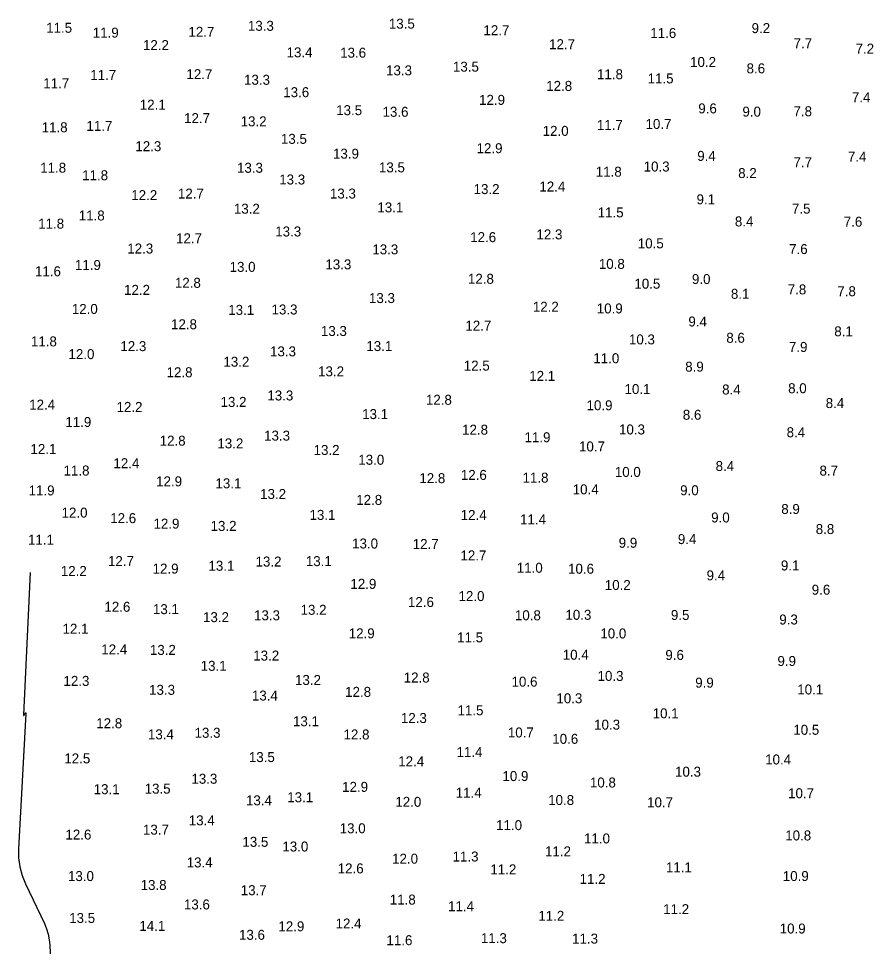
# Model space of a CAD drawing. Extents: x 1023796 to 1112670, y 656573 to 837340.
# Drawn here: x 1112001.4 to 1112430.1, y 656973.6 to 657439 of the extents above; entities that cross this region are included whole.
import ezdxf

# ---------------------------------------------------------------- set-up
doc = ezdxf.new("R2010")
doc.units = 0
doc.layers.add('V-CHAN-CONT-15FT', color=7, linetype='Continuous')
doc.layers.add('V-TOPO-SOUN', color=7, linetype='Continuous')

msp = doc.modelspace()

# ---------------------------------------------------------------- linework, layer by layer
at = {"layer": 'V-CHAN-CONT-15FT'}
msp.add_lwpolyline([(1112007.17, 657161.14), (1112003.86, 657089.72), (1112003.87, 657089.49), (1112003.92, 657089.4), (1112004.02, 657089.44), (1112004.15, 657089.62), (1112004.79, 657090.6), (1112004.93, 657090.78), (1112005.03, 657090.82), (1112005.08, 657090.73), (1112005.08, 657090.51), (1112001.4, 657022.59), (1112001.43, 657018.02), (1112002.02, 657013.57), (1112003.17, 657009.22), (1112004.88, 657004.98), (1112014.39, 656985.07), (1112015.48, 656982.45), (1112016.29, 656979.77), (1112016.83, 656977.01), (1112017.08, 656974.19), (1112017.71, 656958.8)], dxfattribs=at)

# ---------------------------------------------------------------- texts
at = {"layer": 'V-TOPO-SOUN'}
for s, p in [('13.5 ', (1112187.12, 657433.95)), ('11.5 ', (1112015.25, 657431.9)), ('11.9 ', (1112038.62, 657429.48)), ('12.7 ', (1112086.6, 657429.86)), ('13.3 ', (1112116.43, 657432.88)), ('12.7 ', (1112234.56, 657430.68)), ('11.6 ', (1112318.23, 657429.28)), ('9.2', (1112369.05, 657431.73)), ('7.7', (1112390.11, 657424.13)), ('12.2 ', (1112063.8, 657423.21)), ('13.4 ', (1112135.83, 657419.56)), ('13.6 ', (1112162.69, 657419.41)), ('12.7 ', (1112267.48, 657423.66)), ('7.2', (1112421.19, 657421.44)), ('10.2 ', (1112338.2, 657414.73)), ('13.3 ', (1112185.71, 657410.53)), ('13.5 ', (1112219.26, 657412.4)), ('8.6', (1112366.52, 657411.54)), ('11.7 ', (1112037.34, 657408.21)), ('12.7 ', (1112085.6, 657408.63)), ('13.3 ', (1112114.49, 657405.81)), ('11.8 ', (1112291.53, 657408.6)), ('11.5 ', (1112316.89, 657406.49)), ('11.7 ', (1112013.79, 657404.06)), ('12.8 ', (1112266.03, 657402.75)), ('13.6 ', (1112134.15, 657399.59)), ('7.4', (1112419.35, 657397.06)), ('12.1 ', (1112062.21, 657393.32)), ('12.9 ', (1112232.36, 657395.75)), ('9.6', (1112342.31, 657391.46)), ('12.7 ', (1112084.43, 657386.59)), ('13.5 ', (1112160.69, 657390.57)), ('13.6 ', (1112183.95, 657389.76)), ('9.0', (1112364.44, 657389.84)), ('7.8', (1112390.05, 657390.03)), ('11.8 ', (1112012.99, 657381.99)), ('11.7 ', (1112035.46, 657382.7)), ('13.2 ', (1112112.78, 657384.98)), ('11.7 ', (1112291.44, 657383.16)), ('10.7 ', (1112315.85, 657383.65)), ('12.0 ', (1112264.25, 657380.19)), ('13.5 ', (1112132.99, 657376.19)), ('12.3 ', (1112059.98, 657372.51)), ('13.9 ', (1112159.11, 657368.75)), ('12.9 ', (1112231.1, 657371.5)), ('9.4', (1112341.78, 657367.64)), ('7.7', (1112390.06, 657364.47)), ('7.4', (1112417.35, 657367.27)), ('11.8 ', (1112012.24, 657361.71)), ('13.3 ', (1112110.95, 657361.67)), ('13.5 ', (1112182.15, 657361.87)), ('11.8 ', (1112290.89, 657359.71)), ('10.3 ', (1112314.91, 657362.31)), ('8.2', (1112362.32, 657359.02)), ('11.8 ', (1112033.29, 657357.93)), ('13.3 ', (1112132.13, 657355.8)), ('13.2 ', (1112229.62, 657350.98)), ('12.4 ', (1112262.6, 657352.27)), ('12.2 ', (1112057.93, 657347.95)), ('12.7 ', (1112081.32, 657348.73)), ('13.3 ', (1112157.56, 657348.76)), ('9.1', (1112341.44, 657345.87)), ('13.2 ', (1112109.4, 657341.14)), ('13.1 ', (1112181.35, 657341.81)), ('7.5', (1112389.29, 657341.18)), ('11.8 ', (1112031.59, 657337.75)), ('11.5 ', (1112291.86, 657339.29)), ('11.8 ', (1112011.23, 657333.66)), ('8.4', (1112360.66, 657334.77)), ('7.6', (1112415.26, 657334.63)), ('12.7 ', (1112080.39, 657326.31)), ('13.3 ', (1112130.13, 657329.72)), ('12.6 ', (1112227.91, 657326.88)), ('12.3 ', (1112261.15, 657328.26)), ('10.5 ', (1112311.96, 657323.75)), ('12.3 ', (1112055.93, 657321.18)), ('13.3 ', (1112178.83, 657320.75)), ('7.6', (1112387.86, 657320.9)), ('11.9 ', (1112029.67, 657312.92)), ('13.3 ', (1112155.29, 657313.22)), ('10.8 ', (1112292.43, 657313.46)), ('11.6 ', (1112009.64, 657309.77)), ('13.0 ', (1112107.25, 657311.98)), ('12.8 ', (1112079.8, 657303.98)), ('12.8 ', (1112226.78, 657305.99)), ('10.5 ', (1112310.26, 657303.52)), ('9.0', (1112339.12, 657305.87)), ('12.2 ', (1112054.32, 657300.44)), ('8.1', (1112358.67, 657298.46)), ('7.8', (1112387.17, 657300.68)), ('7.8', (1112412.04, 657299.77)), ('13.3 ', (1112177.14, 657296.33)), ('12.0 ', (1112028.11, 657290.87)), ('13.1 ', (1112106.57, 657290.41)), ('13.3 ', (1112128.27, 657290.6)), ('12.2 ', (1112259.32, 657291.97)), ('10.9 ', (1112291.4, 657291.13)), ('9.4', (1112337.34, 657284.57)), ('12.8 ', (1112077.87, 657283.19)), ('13.3 ', (1112153.04, 657279.82)), ('12.7 ', (1112225.49, 657282.5)), ('8.1', (1112410.52, 657279.65)), ('10.3 ', (1112307.53, 657275.59)), ('8.6', (1112356.36, 657276.4)), ('11.8 ', (1112007.59, 657274.6)), ('12.3 ', (1112052.47, 657272.21)), ('13.1 ', (1112175.83, 657272.26)), ('7.9', (1112387.76, 657271.82)), ('12.0 ', (1112026.43, 657268.21)), ('13.3 ', (1112127.52, 657269.59)), ('11.0 ', (1112289.66, 657266.15)), ('13.2 ', (1112104.15, 657264.39)), ('12.5 ', (1112224.69, 657262.44)), ('8.9', (1112335.75, 657261.93)), ('12.8 ', (1112075.63, 657259.12)), ('13.2 ', (1112151.63, 657259.56)), ('12.1 ', (1112257.53, 657257.29)), ('13.3 ', (1112126.18, 657247.47)), ('10.1 ', (1112305.31, 657250.69)), ('8.4', (1112354.27, 657250.46)), ('8.0', (1112387.37, 657251.11)), ('12.4 ', (1112006.74, 657242.89)), ('13.2 ', (1112102.7, 657244.24)), ('12.8 ', (1112205.71, 657245.3)), ('10.9 ', (1112286.26, 657242.56)), ('8.4', (1112406.2, 657243.66)), ('12.2 ', (1112050.54, 657241.72)), ('13.1 ', (1112173.73, 657238.14)), ('8.6', (1112334.55, 657237.8)), ('11.9 ', (1112024.86, 657234.18)), ('12.8 ', (1112223.84, 657230.31)), ('10.3 ', (1112302.55, 657230.42)), ('8.4', (1112386.61, 657229.03)), ('12.8 ', (1112072.18, 657224.8)), ('13.3 ', (1112124.55, 657227.33)), ('11.9 ', (1112255.15, 657226.52)), ('12.1 ', (1112007.37, 657220.63)), ('13.2 ', (1112101.12, 657223.43)), ('13.2 ', (1112149.38, 657220.13)), ('10.7 ', (1112282.48, 657221.91)), ('13.0 ', (1112171.79, 657215.22)), ('11.8 ', (1112023.96, 657209.82)), ('12.4 ', (1112048.98, 657213.49)), ('8.4', (1112351.01, 657212.09)), ('8.7', (1112403.1, 657209.79)), ('12.8 ', (1112202.41, 657205.99)), ('12.6 ', (1112223.23, 657207.62)), ('11.8 ', (1112254.16, 657206.26)), ('10.0 ', (1112300.45, 657209.12)), ('12.9 ', (1112070.39, 657204.4)), ('13.1 ', (1112100.16, 657203.41)), ('11.9 ', (1112006.44, 657199.85)), ('13.2 ', (1112122.55, 657198.06)), ('10.4 ', (1112279.32, 657200.38)), ('9.0', (1112333.22, 657199.94)), ('12.8 ', (1112170.75, 657195.1)), ('12.0 ', (1112022.97, 657188.72)), ('13.1 ', (1112147.31, 657187.57)), ('12.4 ', (1112223.14, 657187.52)), ('8.9', (1112383.93, 657190.54)), ('12.6 ', (1112047.38, 657185.94)), ('12.9 ', (1112069.07, 657183.2)), ('13.2 ', (1112097.7, 657182.05)), ('11.4 ', (1112252.91, 657185.31)), ('9.0', (1112348.77, 657186.28)), ('8.8', (1112401.21, 657180.47)), ('11.1 ', (1112006.12, 657175.13)), ('13.0 ', (1112168.68, 657173.22)), ('12.7 ', (1112199.08, 657172.98)), ('9.9', (1112302.38, 657173.59)), ('9.4', (1112332.06, 657175.43)), ('12.7 ', (1112046.25, 657164.42)), ('13.2 ', (1112120.25, 657164.17)), ('13.1 ', (1112145.48, 657164.38)), ('12.7 ', (1112223.03, 657167.24)), ('12.2 ', (1112022.6, 657159.44)), ('12.9 ', (1112068.63, 657160.63)), ('13.1 ', (1112096.64, 657162.05)), ('11.0 ', (1112251.27, 657161.05)), ('10.6 ', (1112276.99, 657160.56)), ('9.1', (1112383.75, 657162.21)), ('9.4', (1112346.47, 657157.24)), ('12.9 ', (1112167.82, 657152.98)), ('10.2 ', (1112295.42, 657152.4)), ('9.6', (1112399.2, 657150.04)), ('12.0 ', (1112222.06, 657146.85)), ('12.6 ', (1112044.45, 657141.48)), ('13.1 ', (1112068.8, 657140.3)), ('13.2 ', (1112142.84, 657139.96)), ('12.6 ', (1112196.7, 657143.87)), ('13.2 ', (1112093.92, 657136.28)), ('13.3 ', (1112119.5, 657137.21)), ('10.8 ', (1112250.34, 657137.23)), ('10.3 ', (1112275.67, 657137.46)), ('9.5', (1112328.58, 657137.38)), ('9.3', (1112382.94, 657135.1)), ('12.1 ', (1112023.46, 657130.47)), ('12.9 ', (1112167, 657128.17)), ('11.5 ', (1112221.36, 657126.12)), ('10.0 ', (1112293.18, 657128.11)), ('12.4 ', (1112042.89, 657120.1)), ('13.2 ', (1112067.26, 657119.86)), ('13.2 ', (1112119.1, 657117.01)), ('10.4 ', (1112274.33, 657117.42)), ('9.6', (1112325.79, 657117.33)), ('9.9', (1112382.01, 657114.29)), ('13.1 ', (1112092.73, 657111.86)), ('12.3 ', (1112023.92, 657104.31)), ('13.2 ', (1112140.05, 657104.78)), ('12.8 ', (1112194.56, 657106)), ('10.6 ', (1112248.64, 657103.92)), ('10.3 ', (1112291.78, 657106.8)), ('9.9', (1112340.77, 657103.44)), ('13.3 ', (1112066.86, 657099.83)), ('12.8 ', (1112165.19, 657098.8)), ('10.1 ', (1112391.94, 657100.01)), ('13.4 ', (1112118.44, 657096.97)), ('10.3 ', (1112271.13, 657095.59)), ('11.5 ', (1112221.55, 657089.55)), ('13.1 ', (1112139.03, 657084.07)), ('12.3 ', (1112193.15, 657085.69)), ('10.1 ', (1112319.42, 657088.05)), ('12.8 ', (1112040.37, 657083.07)), ('10.3 ', (1112290.07, 657082.36)), ('10.5 ', (1112389.96, 657079.78)), ('13.4 ', (1112066.28, 657077.48)), ('13.3 ', (1112089.66, 657078.28)), ('12.8 ', (1112164.39, 657077.44)), ('10.7 ', (1112246.8, 657078.44)), ('10.6 ', (1112269.08, 657075.24)), ('12.5 ', (1112024.35, 657065.44)), ('13.5 ', (1112116.91, 657066.1)), ('11.4 ', (1112221.06, 657068.62)), ('12.4 ', (1112191.83, 657063.97)), ('10.4 ', (1112375.84, 657064.89)), ('10.9 ', (1112244.09, 657056.57)), ('10.3 ', (1112330.65, 657058.75)), ('13.3 ', (1112088.09, 657055.22)), ('10.8 ', (1112287.95, 657053.35)), ('13.1 ', (1112039.07, 657049.99)), ('13.5 ', (1112064.64, 657050.26)), ('12.9 ', (1112163.68, 657051.16)), ('11.4 ', (1112220.64, 657048.21)), ('10.7 ', (1112387.35, 657047.97)), ('13.4 ', (1112115.46, 657044.37)), ('13.1 ', (1112136.15, 657045.94)), ('12.0 ', (1112190.36, 657043.64)), ('10.8 ', (1112267.01, 657044.57)), ('10.7 ', (1112316.63, 657043.4)), ('13.4 ', (1112086.77, 657034.36)), ('13.7 ', (1112063.79, 657029.69)), ('13.0 ', (1112162.46, 657030.39)), ('11.0 ', (1112240.91, 657031.96)), ('12.6 ', (1112024.9, 657027.22)), ('13.5 ', (1112113.66, 657023.59)), ('11.0 ', (1112285, 657025.29)), ('10.8 ', (1112385.91, 657026.79)), ('13.0 ', (1112133.71, 657021.24)), ('12.0 ', (1112188.74, 657015.14)), ('11.3 ', (1112219.06, 657016.22)), ('11.2 ', (1112265.42, 657018.8)), ('13.4 ', (1112085.71, 657013.25)), ('12.6 ', (1112161.45, 657010.26)), ('11.2 ', (1112238.04, 657009.77)), ('11.1 ', (1112326.06, 657010.78)), ('13.0 ', (1112026.18, 657006.41)), ('11.2 ', (1112282.77, 657005)), ('10.9 ', (1112384.69, 657006.43)), ('13.8 ', (1112062.63, 657001.93)), ('13.7 ', (1112112.84, 656999.33)), ('13.6 ', (1112084.34, 656992.17)), ('11.8 ', (1112187.58, 656994.62)), ('11.4 ', (1112216.82, 656991.3)), ('11.2 ', (1112262.07, 656986.46)), ('11.2 ', (1112324.7, 656989.81)), ('13.5 ', (1112026.78, 656985.39)), ('12.4 ', (1112160.4, 656982.62)), ('14.1 ', (1112061.98, 656981.43)), ('12.9 ', (1112131.71, 656981.21)), ('10.9 ', (1112383.14, 656980.11)), ('13.6 ', (1112111.96, 656976.94)), ('11.6 ', (1112185.92, 656974.24)), ('11.3 ', (1112233.27, 656975.26)), ('11.3 ', (1112279.01, 656975.04))]:
    msp.add_text(s, height=5, dxfattribs=at).set_placement(p)

doc.saveas('drawing.dxf')
